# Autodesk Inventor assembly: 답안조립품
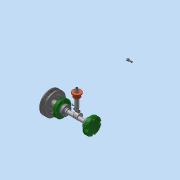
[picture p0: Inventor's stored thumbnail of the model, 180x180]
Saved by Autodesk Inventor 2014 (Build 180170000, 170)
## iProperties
Created: 2016-02
Part Number: 답안조립품
Document SubType Name: Assembly
Designer: SCD-A13
Author: SCD-A13
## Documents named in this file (16)
- C:\Users\SCD-A13\Desktop\460211V1016\답안조립품.iam
- C:\Users\SCD-A13\Desktop\460211V1016\본체.ipt
- C:\Users\SCD-A13\Desktop\460211V1016\V벨트풀리.ipt
- C:\Users\SCD-A13\Desktop\460211V1016\고정핀 1.2 x 10.ipt
- C:\Users\SCD-A13\Desktop\460211V1016\뒤커버.ipt
- C:\Users\SCD-A13\Desktop\460211V1016\링크.ipt
- C:\Users\SCD-A13\Desktop\460211V1016\멈춤나사 M3x8.ipt
- C:\Users\SCD-A13\Desktop\460211V1016\베어링 12 x 32 x 10.ipt
- C:\Users\SCD-A13\Desktop\460211V1016\볼트 M4 x 12.ipt
- C:\Users\SCD-A13\Desktop\460211V1016\부시.ipt
- C:\Users\SCD-A13\Desktop\460211V1016\슬라이드.ipt
- C:\Users\SCD-A13\Desktop\460211V1016\앞커버.ipt
- C:\Users\SCD-A13\Desktop\460211V1016\오일실 12 25 7.ipt
- C:\Users\SCD-A13\Desktop\460211V1016\키 4 x 4 x 10.ipt
- C:\Users\SCD-A13\Desktop\460211V1016\편심축.ipt
- C:\Users\SCD-A13\Desktop\460211V1016\핀 5 x 18.ipt
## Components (4 placed, 4 different names)
1. V벨트풀리:1 — 각도:2
2. 고정핀 1.2 x 10:1
3. ISO 4762 M4 x 12:1
4. 핀 5 x 18:1
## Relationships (1: Angle 1)
- 각도:2 [Angle]: V벨트풀리:1
